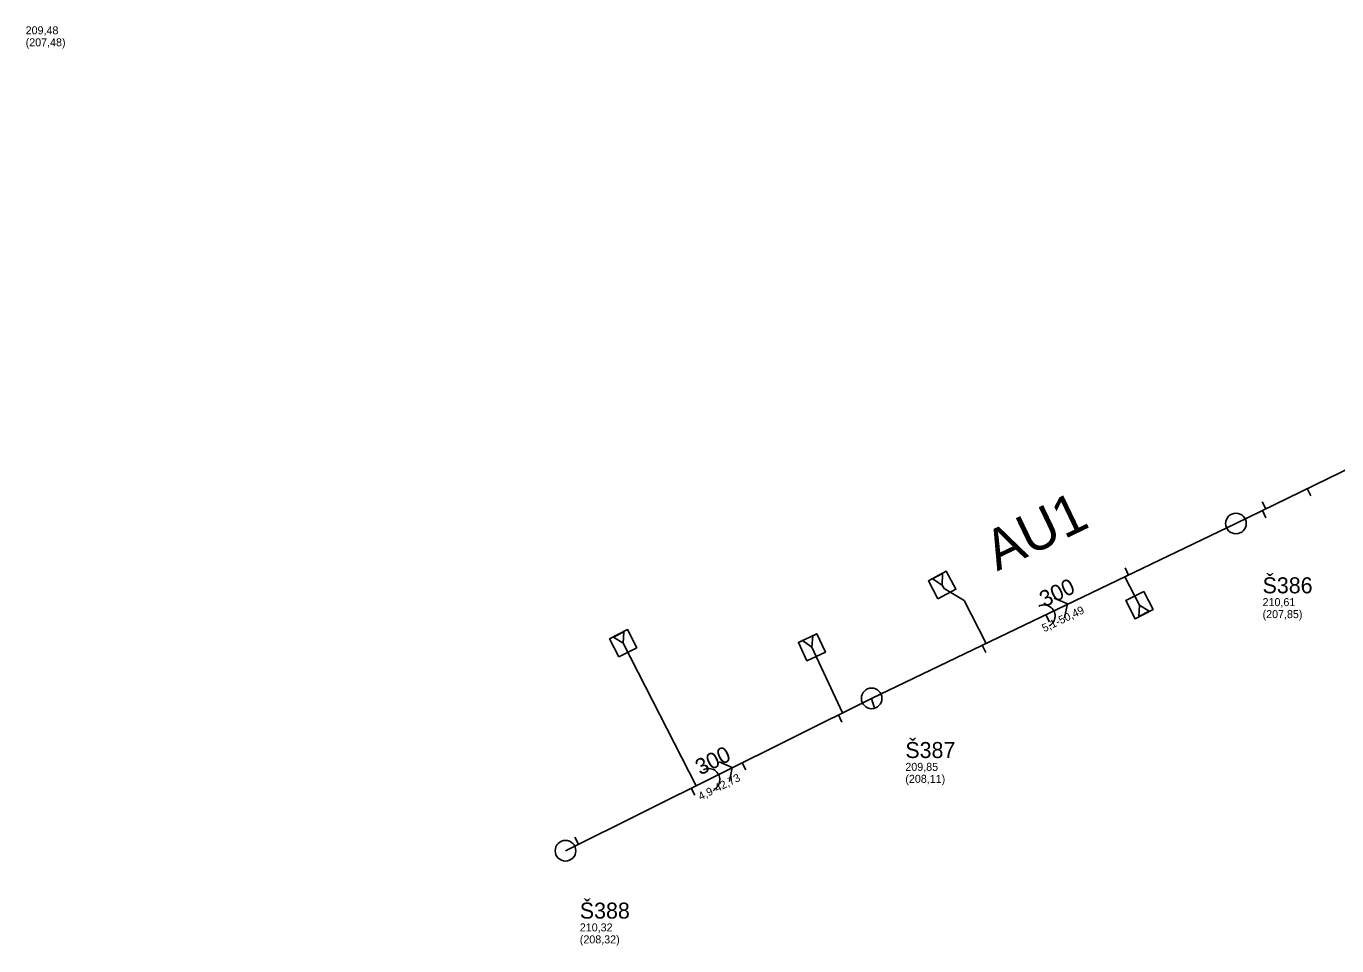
# Model space of a CAD drawing. Extents: x -574467 to -573663, y -1191209 to -1190406.
# Drawn here: x -574050.1 to -573886.4, y -1190924 to -1190809 of the extents above; entities that cross this region are included whole.
import ezdxf

# ---------------------------------------------------------------- set-up
doc = ezdxf.new("R2010")
doc.units = 0
for name, color, linetype in [('Vrstva 1', 7, 'Continuous'), ('Vrstva 12', 7, 'Continuous'), ('Vrstva 15', 7, 'Continuous'), ('Vrstva 29', 7, 'Continuous'), ('Vrstva 35', 7, 'Continuous'), ('Vrstva 41', 7, 'Continuous'), ('Vrstva 44', 7, 'Continuous'), ('Vrstva 45', 7, 'Continuous'), ('Vrstva 56', 7, 'Continuous'), ('Vrstva 57', 7, 'Continuous')]:
    doc.layers.add(name, color=color, linetype=linetype)

# ---------------------------------------------------------------- blocks, each defined once
blk = doc.blocks.new('100')
at = {"layer": 'Vrstva 1'}
blk.add_circle((0, 0), 1.27, dxfattribs=at)
blk = doc.blocks.new('105')
at = {"layer": 'Vrstva 1'}
blk.add_lwpolyline([(-1.27, 1.27), (1.27, 1.27), (1.27, -1.27), (-1.27, -1.27), (-1.27, 1.27)], dxfattribs=at)
blk = doc.blocks.new('106')
at = {"layer": 'Vrstva 1'}
for p, q in [((1.25, 0.72), (0, 0)), ((0, 0), (1.25, -0.72)), ((1.25, -0.72), (1.25, 0.72))]:
    blk.add_line(p, q, dxfattribs=at)
blk = doc.blocks.new('86')
at = {"layer": 'Vrstva 1'}
blk.add_lwpolyline([(0.79, 1.37), (1.89, 0), (0.79, -1.38)], dxfattribs=at)
blk.add_arc((-1.37, 0), 1.37, 270, 90, dxfattribs=at)

msp = doc.modelspace()

# ---------------------------------------------------------------- linework, layer by layer
at = {"layer": 'Vrstva 12'}
for p, q in [((-573890.079, -1190866.809), (-573889.639, -1190867.707)), ((-573895.253, -1190869.341), (-573895.692, -1190868.443)), ((-573895.684, -1190869.552), (-573895.244, -1190870.45)), ((-573912.409, -1190877.616), (-573912.842, -1190876.714)), ((-573912.887, -1190877.845), (-573911.043, -1190881.362)), ((-573922.731, -1190882.573), (-573922.298, -1190883.475)), ((-573966.44, -1190903.957), (-573975.546, -1190886.15)), ((-573948.153, -1190894.849), (-573951.971, -1190886.644)), ((-573930.681, -1190886.392), (-573930.248, -1190887.294)), ((-573944.5, -1190893.03), (-573944.124, -1190894.239)), ((-573948.654, -1190895.099), (-573948.208, -1190895.994)), ((-573960.667, -1190901.082), (-573960.221, -1190901.977)), ((-573967.031, -1190904.251), (-573966.585, -1190905.146)), ((-573981.12, -1190911.268), (-573981.566, -1190910.373))]:
    msp.add_line(p, q, dxfattribs=at)
msp.add_lwpolyline([(-573930.194, -1190886.158), (-573932.922, -1190880.814), (-573935.46, -1190879.297), (-573935.696, -1190878.863)], dxfattribs=at)
at = {"layer": 'Vrstva 15'}
for p, q in [((-573898.99, -1190871.17), (-573855.73, -1190850)), ((-573944.5, -1190893.03), (-573898.99, -1190871.17)), ((-573982.75, -1190912.08), (-573944.5, -1190893.03))]:
    msp.add_line(p, q, dxfattribs=at)

# ---------------------------------------------------------------- block references
at = {"layer": 'Vrstva 12'}
for name, p, xscale, yscale, rotation in [('105', (-573935.696, -1190878.863), 0.9999999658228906, 0.9999999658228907, 117.99999982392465), ('106', (-573935.696, -1190878.863), 0.9999999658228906, 0.9999999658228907, 117.99999982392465), ('105', (-573911.043, -1190881.362), 0.999999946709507, 0.999999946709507, -62.999999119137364), ('106', (-573911.043, -1190881.362), 0.999999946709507, 0.999999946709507, -62.999999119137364), ('105', (-573975.546, -1190886.15), 0.999999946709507, 0.999999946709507, 117.00000088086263), ('106', (-573975.546, -1190886.15), 0.999999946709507, 0.999999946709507, 117.00000088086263), ('105', (-573951.971, -1190886.644), 0.9999999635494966, 0.9999999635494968, 114.99999960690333), ('106', (-573951.971, -1190886.644), 0.9999999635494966, 0.9999999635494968, 114.99999960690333)]:
    msp.add_blockref(name, p, dxfattribs=dict(at, xscale=xscale, yscale=yscale, rotation=rotation))
at = {"layer": 'Vrstva 29'}
for p, xscale, yscale, rotation in [((-573898.99, -1190871.17), 1.0138864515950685, 1.0138864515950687, 27.5653151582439), ((-573944.5, -1190893.03), 1.0138864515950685, 1.0138864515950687, 27.5653151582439), ((-573982.75, -1190912.08), 1.0169561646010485, 1.0169561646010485, -153.0239835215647)]:
    msp.add_blockref('100', p, dxfattribs=dict(at, xscale=xscale, yscale=yscale, rotation=rotation))
at = {"layer": 'Vrstva 41', "xscale": 1.0138864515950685, "yscale": 1.0138864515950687, "rotation": 27.5653151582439}
for p in [(-573921.745, -1190882.1), (-573963.625, -1190902.555)]:
    msp.add_blockref('86', p, dxfattribs=at)

# ---------------------------------------------------------------- texts
at = {"layer": 'Vrstva 35'}
msp.add_text('AU1', height=5, rotation=25.66, dxfattribs=at).set_placement((-573928.811, -1190877.175))
at = {"layer": 'Vrstva 44'}
for rotation, p in [(25.66, (-573922.928, -1190881.669)), (26.48, (-573965.905, -1190902.684))]:
    msp.add_text('300', height=2, rotation=rotation, dxfattribs=at).set_placement(p)
at = {"layer": 'Vrstva 45'}
for s, rotation, p in [('5,1-50,49', 25.66, (-573922.932, -1190884.776)), ('4,9-42,73', 26.48, (-573965.87, -1190905.798))]:
    msp.add_text(s, height=1, rotation=rotation, dxfattribs=at).set_placement(p)
at = {"layer": 'Vrstva 56'}
for s, p in [('209,48 ', (-574050.19, -1190810.02)), ('(207,48)', (-574050.19, -1190811.52)), ('210,61 ', (-573895.66, -1190881.5)), ('(207,85)', (-573895.66, -1190883)), ('209,85 ', (-573940.29, -1190902.09)), ('(208,11)', (-573940.29, -1190903.59)), ('210,32 ', (-573980.96, -1190922.16)), ('(208,32)', (-573980.96, -1190923.66))]:
    msp.add_text(s, height=1, dxfattribs=at).set_placement(p)
at = {"layer": 'Vrstva 57'}
for s, p in [('Š386', (-573895.66, -1190879.9)), ('Š387', (-573940.29, -1190900.49)), ('Š388', (-573980.96, -1190920.56))]:
    msp.add_text(s, height=2, dxfattribs=at).set_placement(p)

doc.saveas('drawing.dxf')
